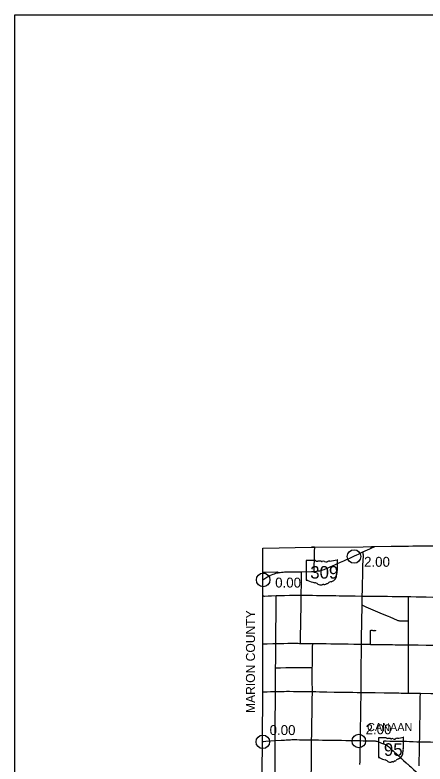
# Model space of a CAD drawing. Extents: x 1813937 to 1948437, y 826606 to 1022856.
# Drawn here: x 1813937 to 1859353, y 939932 to 1022856 of the extents above; entities that cross this region are included whole.
import ezdxf

# ---------------------------------------------------------------- set-up
doc = ezdxf.new("R2010")
doc.units = 0
for name, color, linetype in [('Default', 7, 'Continuous'), ('GM_X_Adjacent_County_Text', 7, 'Continuous'), ('GM_X_County', 7, 'Continuous'), ('GM_X_County_Road', 7, 'Continuous'), ('GM_X_State_Route', 7, 'Continuous'), ('GM_X_State_Shield', 7, 'Continuous'), ('GM_X_Township', 7, 'Continuous'), ('GM_X_Township_Road', 7, 'Continuous'), ('GM_X_Township_Text', 7, 'Continuous'), ('SC_Scratch1', 7, 'Continuous')]:
    doc.layers.add(name, color=color, linetype=linetype)

msp = doc.modelspace()

# ---------------------------------------------------------------- linework, layer by layer
at = {"layer": 'Default'}
for centre in [(1851490, 962906), (1841426, 960316), (1841391, 942390), (1841391, 942390), (1852020, 942476)]:
    msp.add_circle(centre, 750, dxfattribs=at)
at = {"layer": 'GM_X_County'}
msp.add_lwpolyline([(1841249, 932050), (1841362, 942439), (1841377, 947941), (1841392, 953202), (1841402, 956488), (1841397, 958575), (1841394, 960342), (1841392, 961182), (1841387, 963824), (1846780, 963929), (1847071, 963938), (1852487, 963992), (1853408, 964004), (1853786, 964009), (1855618, 964050), (1860298, 964101)], dxfattribs=at)
at = {"layer": 'GM_X_County_Road'}
for points in [[(1853373, 963817), (1853375, 963837), (1853377, 963853), (1853378, 963867), (1853381, 963885), (1853390, 963915), (1853400, 963949), (1853409, 963974)], [(1852406, 958524), (1852407, 958550), (1852407, 958648), (1852417, 959074), (1852422, 959304), (1852425, 959468), (1852431, 959714), (1852436, 959911), (1852440, 960091), (1852452, 960632), (1852455, 960845), (1852458, 961026), (1852463, 961206), (1852466, 961354), (1852473, 961616), (1852475, 961764), (1852479, 961961), (1852483, 962091), (1852488, 962288), (1852491, 962403), (1852495, 962485), (1852502, 962567), (1852512, 962648), (1852518, 962689), (1852523, 962750), (1852529, 962826), (1852531, 962880), (1852527, 962951), (1852521, 963061), (1852517, 963173), (1852515, 963242), (1852512, 963301), (1852508, 963340), (1852501, 963364), (1852495, 963379), (1852482, 963411)], [(1842871, 958572), (1842943, 958574), (1843467, 958592), (1843795, 958605), (1844337, 958622), (1844616, 958625), (1845108, 958622), (1845404, 958622), (1845650, 958621)], [(1845650, 958621), (1846175, 958620), (1846897, 958613), (1847340, 958606), (1848028, 958595), (1848652, 958584), (1849094, 958577), (1849291, 958576), (1849488, 958573), (1849833, 958567), (1850276, 958561), (1850637, 958556), (1850998, 958549), (1851605, 958541), (1852376, 958524), (1852406, 958524)], [(1841368, 958601), (1841416, 958567), (1841440, 958551), (1841466, 958540), (1841500, 958533), (1841565, 958530), (1841975, 958543), (1842352, 958555), (1842871, 958572)], [(1852388, 957514), (1852390, 957647), (1852396, 957910), (1852398, 958107), (1852404, 958388), (1852406, 958524)], [(1852406, 958524), (1852606, 958527), (1852967, 958522), (1853590, 958516), (1854263, 958508), (1854821, 958502), (1855182, 958498), (1855723, 958490), (1855953, 958487), (1856330, 958485), (1857003, 958476), (1857315, 958470), (1857510, 958468)], [(1857510, 958468), (1857774, 958464), (1858381, 958450), (1859497, 958428), (1860219, 958415), (1860263, 958416)], [(1857520, 955791), (1857518, 956073), (1857517, 956828), (1857517, 957452), (1857511, 958240), (1857510, 958436), (1857510, 958468)], [(1852307, 953199), (1852310, 953285), (1852317, 953662), (1852322, 953974), (1852333, 954531), (1852341, 955007), (1852350, 955433), (1852354, 955647), (1852355, 955761), (1852358, 955942), (1852363, 956122), (1852366, 956270), (1852370, 956466), (1852374, 956712), (1852378, 957008), (1852383, 957270), (1852388, 957514)], [(1852388, 957514), (1852417, 957502), (1852781, 957351), (1853566, 957016), (1854593, 956576), (1855272, 956286), (1855453, 956209), (1855876, 956028), (1856268, 955857), (1856344, 955828), (1856392, 955815), (1856441, 955807), (1856523, 955802), (1857278, 955795), (1857492, 955792), (1857520, 955791)], [(1857535, 953123), (1857535, 953163), (1857533, 953474), (1857533, 953573), (1857530, 953835), (1857530, 954032), (1857526, 954341), (1857525, 954521), (1857523, 954621), (1857523, 954630), (1857523, 954662), (1857522, 954793), (1857521, 954941), (1857520, 954974), (1857520, 955072), (1857519, 955236), (1857520, 955483), (1857521, 955712), (1857520, 955791)], [(1842823, 953269), (1842895, 953273), (1843187, 953278), (1843482, 953283), (1843712, 953289), (1844171, 953301), (1844417, 953299), (1844728, 953299), (1845056, 953294), (1845303, 953294), (1845434, 953293), (1845563, 953291)], [(1845563, 953291), (1845680, 953290), (1845991, 953290), (1846336, 953289), (1846598, 953289), (1846910, 953285)], [(1846910, 953285), (1847041, 953284), (1847320, 953280), (1847812, 953272), (1848386, 953262), (1848928, 953253), (1849682, 953242), (1850125, 953233), (1850831, 953221), (1851470, 953213), (1851995, 953202), (1852307, 953199)], [(1852275, 947862), (1852275, 947904), (1852277, 948166), (1852279, 948445), (1852280, 948593), (1852282, 948839), (1852284, 949118), (1852285, 949364), (1852287, 949643), (1852289, 949856), (1852289, 950118), (1852292, 950479), (1852293, 950611), (1852294, 950988), (1852295, 951300), (1852296, 951464), (1852299, 951677), (1852302, 951956), (1852304, 952235), (1852303, 952514), (1852308, 953055), (1852307, 953199)], [(1852307, 953199), (1852504, 953195), (1852799, 953190), (1853258, 953183), (1853321, 953182)], [(1853321, 953182), (1853652, 953178), (1854160, 953171), (1855456, 953151), (1855735, 953148), (1856063, 953143), (1856523, 953136), (1857244, 953126), (1857535, 953123)], [(1857525, 947784), (1857525, 947829), (1857525, 947976), (1857528, 948814), (1857529, 949322), (1857531, 950127), (1857531, 950471), (1857530, 950717), (1857529, 950881), (1857533, 951259), (1857535, 951686), (1857534, 951899), (1857535, 952096), (1857535, 952621), (1857537, 952998), (1857535, 953123)], [(1857535, 953123), (1857638, 953122), (1858590, 953112), (1859475, 953106), (1860033, 953098), (1860279, 953094), (1860722, 953087), (1861083, 953078), (1861561, 953071)], [(1852194, 942521), (1852194, 942655), (1852196, 942769), (1852198, 942933), (1852202, 943114), (1852204, 943196), (1852206, 943425), (1852210, 943770), (1852214, 944065), (1852219, 944361), (1852226, 944803), (1852229, 944984), (1852231, 945230), (1852236, 945444), (1852239, 945625), (1852242, 945886), (1852246, 946148), (1852248, 946280), (1852255, 946575), (1852268, 947288), (1852273, 947658), (1852275, 947862)], [(1852275, 947862), (1852571, 947859), (1853096, 947849), (1853834, 947836), (1854835, 947819), (1855851, 947801), (1856442, 947795), (1856721, 947794), (1857410, 947786), (1857525, 947784)], [(1857525, 947784), (1857918, 947778), (1858558, 947768), (1858837, 947762)], [(1858837, 947762), (1860001, 947739), (1860542, 947729), (1861455, 947708)], [(1846744, 937289), (1846745, 937386), (1846749, 937632), (1846751, 937879), (1846755, 938518), (1846759, 938879), (1846764, 939371), (1846766, 939650), (1846769, 939830), (1846771, 939945), (1846771, 940142), (1846772, 940470), (1846776, 940765), (1846777, 940978), (1846779, 941142), (1846780, 941405), (1846782, 941634), (1846785, 941946), (1846787, 942126), (1846788, 942340), (1846790, 942611)], [(1852151, 939889), (1852157, 940217), (1852158, 940315), (1852159, 940396), (1852163, 940577), (1852171, 940905), (1852175, 941151), (1852182, 941463), (1852186, 941693), (1852191, 941907), (1852192, 941959), (1852193, 942002), (1852194, 942033), (1852195, 942082), (1852195, 942147), (1852196, 942196), (1852197, 942262), (1852196, 942327), (1852196, 942394), (1852194, 942507), (1852194, 942521)], [(1854769, 942173), (1854769, 942179), (1854772, 942222), (1854773, 942245), (1854774, 942278), (1854773, 942377), (1854773, 942426), (1854774, 942442), (1854778, 942457), (1854785, 942470), (1854796, 942479), (1854810, 942486), (1854825, 942489), (1854841, 942490), (1854857, 942490), (1854922, 942488), (1855053, 942485), (1855463, 942479), (1855775, 942472), (1856070, 942467), (1856218, 942464), (1856464, 942461), (1856775, 942455), (1857316, 942444), (1857628, 942434), (1858037, 942419), (1858431, 942405), (1858756, 942397)], [(1858756, 942397), (1858775, 942396), (1859005, 942391), (1859480, 942381), (1859759, 942376), (1859972, 942371), (1860267, 942366), (1860562, 942361), (1860789, 942359)]]:
    msp.add_lwpolyline(points, dxfattribs=at)
at = {"layer": 'GM_X_State_Route'}
for points in [[(1851809, 963104), (1851980, 963182), (1852482, 963411), (1852741, 963530), (1852995, 963644), (1853249, 963761), (1853373, 963817), (1853728, 963978)], [(1848710, 961697), (1848842, 961756), (1849111, 961878), (1849440, 962027), (1849664, 962130), (1849978, 962271), (1850352, 962441), (1850665, 962584), (1851009, 962740), (1851532, 962978), (1851809, 963104)], [(1841375, 960325), (1841849, 960610), (1842048, 960725), (1842179, 960792), (1842357, 960876), (1842524, 960944), (1842663, 960994), (1842835, 961047), (1842977, 961086), (1843075, 961107), (1843121, 961118), (1843299, 961150), (1843445, 961171), (1843624, 961188), (1843772, 961195), (1844674, 961212), (1845396, 961223), (1845676, 961227), (1846774, 961244), (1847004, 961250), (1847082, 961254), (1847201, 961260), (1847348, 961276), (1847527, 961302), (1847705, 961336), (1847864, 961374), (1848022, 961420), (1848194, 961477), (1848347, 961536), (1848513, 961608), (1848710, 961697)], [(1841298, 942429), (1841481, 942439), (1841710, 942452), (1842250, 942486), (1842755, 942519), (1842807, 942522), (1843413, 942561), (1843773, 942582), (1843986, 942595), (1844444, 942622), (1844592, 942630), (1844723, 942634), (1844904, 942635), (1845166, 942632), (1845462, 942626), (1845708, 942624), (1846200, 942617), (1846790, 942611), (1846840, 942610), (1847283, 942604), (1847545, 942598), (1848005, 942591), (1848316, 942585), (1848628, 942580), (1849022, 942572), (1849497, 942565), (1850104, 942555), (1850580, 942545), (1850842, 942542), (1850864, 942542)], [(1850864, 942542), (1851318, 942533), (1851613, 942529), (1851713, 942527)], [(1851713, 942527), (1851892, 942524), (1852188, 942521), (1852194, 942521), (1852515, 942517), (1852549, 942517), (1852580, 942516), (1852645, 942514), (1852759, 942513), (1853054, 942508), (1853300, 942505), (1853661, 942501), (1853744, 942499), (1853793, 942495), (1853842, 942488), (1853891, 942479), (1853938, 942466), (1854001, 942447), (1854110, 942409), (1854527, 942259), (1854769, 942173), (1854882, 942132), (1854959, 942103), (1855004, 942083), (1855048, 942059), (1855090, 942032), (1855129, 942003), (1855193, 941951), (1855292, 941864), (1855511, 941666), (1855658, 941535), (1855829, 941382), (1856012, 941217), (1856145, 941096), (1856352, 940908), (1856533, 940742), (1856612, 940668)], [(1856612, 940668), (1856761, 940529), (1856978, 940328), (1857255, 940073), (1857376, 939962), (1857441, 939903), (1857617, 939744), (1857765, 939609), (1858081, 939323), (1858374, 939060), (1858608, 938848)]]:
    msp.add_lwpolyline(points, dxfattribs=at)
at = {"layer": 'GM_X_State_Shield'}
for p, q in [((1846177, 962423), (1846177, 960309)), ((1847230, 962459), (1846211, 962459)), ((1849657, 961406), (1849657, 962511)), ((1849657, 961406), (1849657, 961406)), ((1856979, 941782), (1856979, 942887)), ((1854195, 942799), (1854195, 940685)), ((1855038, 942835), (1854222, 942835)), ((1856979, 941782), (1856979, 941782))]:
    msp.add_line(p, q, dxfattribs=at)
for centre, radius, start, end in [((1855988, 945716), 2953, 275.84447, 288.90645), ((1856949, 942892), 31, 351.86209, 97.738), ((1854227, 942803), 32.3, 98.1301, 188.1301), ((1855232, 943080), 313, 231.61951, 271.11188), ((1855336, 941649), 1123, 80.48669, 94.98827), ((1855591, 942814), 90.3, 219.79206, 297.10237), ((1855723, 942570), 188, 54.46668, 119.14113), ((1855966, 942905), 226, 233.85621, 294.82819), ((1856364, 942190), 594, 97.34618, 120.76885), ((1856153, 941179), 739, 292.30889, 8.98584), ((1857090, 941319), 210, 136.8065, 186.92959), ((1856972, 941701), 48, 107.94398, 210.33697), ((1856667, 941561), 288, 340.03296, 23.64957), ((1856946, 941778), 33.2, 289.60381, 7.73413), ((1854227, 940681), 32.5, 171.95839, 258.30661), ((1854232, 940897), 248, 267.33899, 280.60386), ((1854283, 940564), 89.5, 29.74838, 93.27175), ((1855414, 942462), 2132, 240.41292, 257.1985), ((1854778, 939736), 667, 47.18416, 75.83597), ((1856464, 940092), 404, 94.40312, 142.57675), ((1855499, 940553), 423, 230.70037, 286.29184), ((1855744, 939822), 348, 85.69512, 111.20995), ((1855775, 940395), 226, 268.77702, 315.54927), ((1855979, 940190), 63.5, 65.75173, 132.64842), ((1855952, 940481), 239, 282.87319, 323.27711)]:
    msp.add_arc(centre, radius, start, end, dxfattribs=at)
for centre, major_axis, start_param, end_param in [((1846217, 962427), (40.3, 0), 1.712693, 3.28349), ((1847473, 962704), (391, 0), 4.042523, 4.731795), ((1847603, 961273), (1404, 0), 1.404758, 1.657858), ((1847921, 962438), (113, 0), 3.836095, 5.185415), ((1848087, 962194), (235, 0), 0.950623, 2.079405), ((1848390, 962529), (282, 0), 4.081561, 5.145723), ((1848888, 961814), (743, 0), 1.699011, 2.107814), ((1848417, 965340), (3691, 0), 4.814394, 5.042369), ((1849619, 962516), (38.7, 0), 6.141152, 7.989035), ((1849648, 961325), (60, 0), 1.883978, 3.671073), ((1849267, 961185), (360, 0), 5.934695, 6.695948), ((1849616, 961402), (41.5, 0), 5.05454, 6.418171), ((1846217, 960305), (40.7, 0), 3.00124, 4.508301), ((1846223, 960521), (310, 0), 4.665946, 4.897461), ((1846287, 960188), (112, 0), 0.519207, 1.627899), ((1848624, 960803), (923, 0), 5.101752, 6.440018), ((1849796, 960943), (262, 0), 2.387724, 3.262537), ((1847700, 962086), (2665, 0), 4.195997, 4.488961), ((1846905, 959360), (834, 0), 0.823519, 1.323587), ((1847807, 960177), (529, 0), 4.026481, 4.996735), ((1848113, 959446), (435, 0), 1.495662, 1.94098), ((1848152, 960019), (282, 0), 4.691044, 5.507374), ((1848407, 959814), (79.4, 0), 1.147584, 2.315152), ((1848373, 960105), (298, 0), 4.937069, 5.64225), ((1849013, 959716), (506, 0), 1.647645, 2.488434)]:
    msp.add_ellipse(centre, major_axis=major_axis, ratio=0.8, start_param=start_param, end_param=end_param, dxfattribs=at)
at = {"layer": 'GM_X_Township'}
msp.add_lwpolyline([(1841387, 963824), (1846780, 963929), (1847071, 963938), (1852487, 963992), (1853408, 964004), (1853786, 964009), (1855618, 964050), (1860298, 964101), (1862894, 964131), (1865546, 964151), (1868643, 964155), (1868586, 961770), (1868495, 957891), (1868480, 956467), (1868459, 955370), (1868335, 951151), (1868323, 950291), (1862794, 950174), (1862758, 947658), (1862681, 942300), (1862643, 939637)], dxfattribs=at)
at = {"layer": 'GM_X_Township_Road'}
for points in [[(1846984, 963939), (1846923, 963935), (1846841, 963930), (1846809, 963931), (1846792, 963933), (1846779, 963935), (1846772, 963938), (1846765, 963942)], [(1847120, 963897), (1847117, 963903), (1847113, 963910), (1847107, 963917), (1847100, 963924), (1847087, 963932), (1847071, 963938), (1847054, 963940), (1847022, 963941), (1846984, 963939)], [(1847082, 961254), (1847083, 961298), (1847086, 961527), (1847087, 961708), (1847092, 962003), (1847098, 962413), (1847104, 962757), (1847111, 963167), (1847119, 963578), (1847131, 963823), (1847129, 963860), (1847128, 963870), (1847126, 963881), (1847123, 963889), (1847120, 963897)], [(1855601, 964061), (1855612, 964055), (1855624, 964052), (1855640, 964050), (1855755, 964047), (1856329, 964055), (1856608, 964056), (1856903, 964058), (1857526, 964065), (1858001, 964070), (1858591, 964078), (1858689, 964080), (1858755, 964080), (1858951, 964083), (1859771, 964094), (1860296, 964103)], [(1841379, 961184), (1841667, 961183), (1842953, 961207), (1842986, 961205), (1843003, 961201), (1843018, 961193), (1843032, 961182), (1843043, 961168), (1843051, 961153), (1843075, 961107)], [(1845650, 958621), (1845651, 958739), (1845651, 958821), (1845651, 958907), (1845651, 959115), (1845652, 959246), (1845656, 959412), (1845656, 959539), (1845658, 959634), (1845660, 959718), (1845662, 959852), (1845662, 959951), (1845663, 960148), (1845664, 960263), (1845666, 960361), (1845667, 960459), (1845669, 960673), (1845673, 960886), (1845675, 961099), (1845675, 961190), (1845676, 961227)], [(1845632, 957512), (1845636, 957690), (1845642, 958018), (1845644, 958247), (1845650, 958608), (1845650, 958621)], [(1842823, 953269), (1842825, 953508), (1842828, 954082), (1842830, 954345), (1842832, 954476), (1842837, 954640), (1842839, 954935), (1842843, 955214), (1842846, 955477), (1842848, 955674), (1842849, 956002), (1842851, 956231), (1842851, 956510), (1842855, 956707), (1842858, 957002), (1842858, 957134), (1842860, 957298), (1842864, 957577), (1842866, 957757), (1842867, 957970), (1842868, 958134), (1842871, 958495), (1842871, 958544), (1842871, 958572)], [(1845562, 953524), (1845566, 953837), (1845570, 954083), (1845573, 954280), (1845578, 954607), (1845582, 954935), (1845590, 955263), (1845595, 955640), (1845601, 955968), (1845609, 956477), (1845617, 956821), (1845624, 957231), (1845629, 957411), (1845632, 957512)], [(1853321, 953182), (1853321, 953211), (1853322, 953539), (1853326, 954179), (1853328, 954425), (1853328, 954655), (1853329, 954676)], [(1853329, 954676), (1853330, 954704), (1853334, 954719), (1853347, 954729), (1853363, 954733), (1853428, 954733), (1853457, 954734), (1853501, 954734), (1853590, 954731), (1853630, 954729), (1853648, 954728), (1853727, 954728), (1853773, 954729), (1853787, 954730), (1853802, 954732), (1853818, 954735), (1853823, 954735), (1853829, 954735), (1853834, 954735), (1853839, 954734), (1853844, 954733), (1853849, 954731), (1853853, 954729), (1853857, 954727), (1853859, 954724), (1853861, 954721), (1853863, 954718), (1853863, 954713), (1853864, 954709), (1853863, 954705), (1853863, 954702), (1853861, 954698), (1853857, 954694), (1853854, 954693), (1853849, 954693), (1853843, 954693), (1853839, 954694), (1853835, 954695), (1853828, 954698), (1853825, 954700), (1853821, 954702), (1853816, 954708), (1853813, 954712)], [(1841344, 953239), (1841510, 953238), (1841856, 953244), (1842500, 953261), (1842780, 953268), (1842823, 953269)], [(1842808, 950593), (1842809, 950801), (1842811, 951129), (1842813, 951375), (1842814, 951589), (1842816, 952015), (1842818, 952261), (1842820, 952573), (1842823, 952950), (1842823, 953213), (1842823, 953269)], [(1845563, 953291), (1845562, 953312), (1845561, 953329), (1845561, 953427), (1845562, 953524)], [(1846871, 950623), (1846872, 950769), (1846874, 950982), (1846879, 951311), (1846882, 951524), (1846888, 951885), (1846896, 952509), (1846903, 952903), (1846909, 953248), (1846910, 953285)], [(1842791, 947962), (1842791, 948078), (1842791, 948209), (1842792, 948357), (1842795, 948537), (1842798, 948800), (1842800, 949013), (1842803, 949308), (1842804, 949522), (1842805, 949718), (1842807, 950014), (1842808, 950325), (1842808, 950506), (1842808, 950593)], [(1842808, 950593), (1842829, 950593), (1842886, 950594), (1843362, 950599), (1843937, 950603), (1844611, 950608), (1844905, 950613), (1845167, 950612), (1845314, 950613), (1845593, 950617), (1845840, 950615), (1846234, 950617), (1846842, 950623), (1846871, 950623)], [(1846876, 947949), (1846876, 948028), (1846874, 948389), (1846870, 948767), (1846869, 949539), (1846869, 949801), (1846866, 949998), (1846868, 950113), (1846868, 950211), (1846867, 950277), (1846866, 950408), (1846871, 950605), (1846871, 950623)], [(1841322, 947936), (1841867, 947941), (1842228, 947949), (1842736, 947960), (1842791, 947962)], [(1842764, 945077), (1842764, 945109), (1842767, 945306), (1842768, 945388), (1842769, 945519), (1842771, 945699), (1842774, 945962), (1842776, 946191), (1842778, 946552), (1842781, 946683), (1842784, 946848), (1842788, 947307), (1842789, 947602), (1842790, 947766), (1842791, 947930), (1842791, 947962)], [(1842791, 947962), (1843097, 947970), (1843737, 947977), (1843994, 947981)], [(1843994, 947981), (1844113, 947983), (1844327, 947983), (1844802, 947978), (1845180, 947971), (1845475, 947968), (1845787, 947963), (1846574, 947954), (1846876, 947949)], [(1846790, 942611), (1846790, 942645), (1846793, 942760), (1846798, 943006), (1846806, 943350), (1846813, 943794), (1846817, 944023), (1846821, 944286), (1846825, 944499), (1846834, 944893), (1846839, 945172), (1846843, 945435), (1846849, 945845), (1846850, 945927), (1846851, 946009), (1846855, 946371), (1846858, 946551), (1846861, 946748), (1846865, 946978), (1846869, 947290), (1846874, 947618), (1846876, 947766), (1846876, 947949)], [(1846876, 947949), (1846951, 947948), (1847263, 947943), (1847673, 947934), (1848461, 947917), (1849297, 947901), (1850396, 947885), (1851348, 947872), (1851840, 947864), (1852260, 947862), (1852275, 947862)], [(1858756, 942397), (1858763, 942760), (1858781, 944006), (1858791, 944596), (1858797, 944989), (1858802, 945284), (1858807, 945694), (1858814, 946071), (1858820, 946513), (1858824, 946841), (1858833, 947349), (1858837, 947709), (1858837, 947762)], [(1842755, 942519), (1842755, 942550), (1842756, 942730), (1842757, 943026), (1842759, 943255), (1842763, 943879), (1842763, 944404), (1842762, 944568), (1842763, 944781), (1842764, 945077)], [(1842730, 937328), (1842731, 937497), (1842732, 937907), (1842735, 938153), (1842739, 938596), (1842740, 938875), (1842741, 939072), (1842743, 939252), (1842745, 939597), (1842748, 940007), (1842748, 940269), (1842750, 940762), (1842751, 941073), (1842752, 941303), (1842754, 941828), (1842755, 942287), (1842755, 942452), (1842755, 942519)], [(1858694, 939749), (1858700, 940073), (1858705, 940319), (1858726, 941138), (1858749, 942055), (1858756, 942397)]]:
    msp.add_lwpolyline(points, dxfattribs=at)
at = {"layer": 'SC_Scratch1'}
msp.add_lwpolyline([(1813937, 826606), (1813937, 1022856), (1948437, 1022856), (1948437, 826606)], close=True, dxfattribs=at)

# ---------------------------------------------------------------- texts
at = {"layer": 'Default'}
for s, p in [('2.00', (1852603, 961766)), ('0.00', (1842757, 959467)), ('0.00', (1842141, 943140)), ('2.00', (1852770, 943226))]:
    msp.add_text(s, height=1100, dxfattribs=at).set_placement(p)
at = {"layer": 'GM_X_Adjacent_County_Text'}
msp.add_text('MARION COUNTY', height=1000, rotation=90, dxfattribs=at).set_placement((1840519, 945579))
at = {"layer": 'GM_X_State_Shield'}
for s, p in [('309', (1846641, 960458)), ('95', (1854796, 940834))]:
    msp.add_text(s, height=1392.2, dxfattribs=at).set_placement(p)
at = {"layer": 'GM_X_Township_Text'}
msp.add_text('CANAAN', height=900, rotation=0.00001, dxfattribs=at).set_placement((1852937, 943571))

doc.saveas('drawing.dxf')
